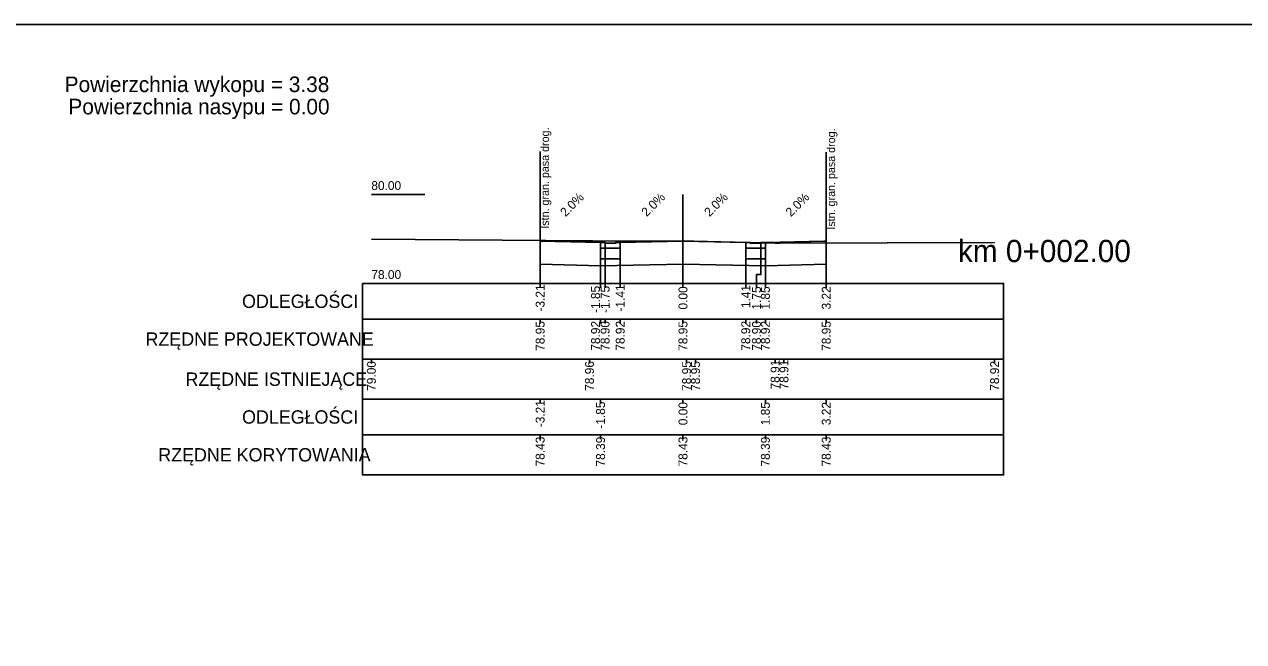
# Model space of a CAD drawing. Extents: x 7492871 to 7493499, y 5802964 to 5802992.
# Drawn here: x 7493302.12 to 7493329.51, y 5802978.41 to 5802992.28 of the extents above; entities that cross this region are included whole.
import ezdxf

# ---------------------------------------------------------------- set-up
doc = ezdxf.new("R2010")
doc.units = 0
for name, color, linetype in [('_wydruk', 7, 'Continuous'), ('d_pop_nasyp_opis', 7, 'Continuous'), ('d_pop_wykop_opis', 7, 'Continuous'), ('opisy_ramki_pop', 7, 'Continuous'), ('pop_comp_kostka', 7, 'Continuous'), ('pop_comp_lawa', 7, 'Continuous'), ('pop_comp_scieralna', 7, 'Continuous'), ('pop_granica_istn', 7, 'Continuous'), ('pop_opis', 7, 'Continuous'), ('pop_os', 7, 'Continuous'), ('pop_pikietaz', 7, 'Continuous'), ('pop_teren', 7, 'Continuous')]:
    doc.layers.add(name, color=color, linetype=linetype)

msp = doc.modelspace()

# ---------------------------------------------------------------- linework, layer by layer
msp.add_lwpolyline([(7493313.708, 5802987.41), (7493315.011, 5802987.384), (7493315.066, 5802987.383), (7493315.162, 5802987.383), (7493315.166, 5802987.383), (7493315.167, 5802987.363), (7493315.396, 5802987.363), (7493315.406, 5802987.363), (7493315.407, 5802987.383), (7493315.503, 5802987.383), (7493315.507, 5802987.383), (7493316.86, 5802987.41), (7493316.917, 5802987.411), (7493316.975, 5802987.41), (7493318.327, 5802987.383), (7493318.423, 5802987.383), (7493318.427, 5802987.383), (7493318.428, 5802987.363), (7493318.438, 5802987.363), (7493318.667, 5802987.363), (7493318.668, 5802987.383), (7493318.672, 5802987.383), (7493318.768, 5802987.383), (7493320.08, 5802987.409), (7493320.135, 5802987.41)])
at = {"layer": '_wydruk'}
msp.add_lwpolyline([(7492871.369, 5802992.281), (7493499.283, 5802992.281), (7493499.283, 5802963.881), (7492871.369, 5802963.881)], close=True, dxfattribs=at)
at = {"layer": 'opisy_ramki_pop'}
for points in [[(7493313.708, 5802986.89), (7493313.708, 5802986.659), (7493313.708, 5802986.659), (7493313.708, 5802986.459)], [(7493315.066, 5802986.854), (7493315.066, 5802986.659), (7493315.066, 5802986.659), (7493315.066, 5802986.459)], [(7493316.917, 5802986.891), (7493316.917, 5802986.659), (7493316.917, 5802986.659), (7493316.917, 5802986.459)], [(7493318.768, 5802986.854), (7493318.768, 5802986.659), (7493318.768, 5802986.659), (7493318.768, 5802986.459)], [(7493320.135, 5802986.89), (7493320.135, 5802986.659), (7493320.135, 5802986.659), (7493320.135, 5802986.459)]]:
    msp.add_lwpolyline(points, dxfattribs=at)
at = {"layer": 'pop_comp_kostka'}
for p, q in [((7493315.166, 5802987.383), (7493315.066, 5802987.383)), ((7493315.066, 5802987.383), (7493315.066, 5802987.253)), ((7493315.167, 5802987.363), (7493315.166, 5802987.383)), ((7493315.407, 5802987.383), (7493315.406, 5802987.363)), ((7493315.507, 5802987.383), (7493315.407, 5802987.383)), ((7493315.507, 5802987.253), (7493315.507, 5802987.383)), ((7493318.427, 5802987.383), (7493318.327, 5802987.383)), ((7493318.327, 5802987.383), (7493318.327, 5802987.253)), ((7493318.428, 5802987.363), (7493318.427, 5802987.383)), ((7493318.668, 5802987.383), (7493318.667, 5802987.363)), ((7493318.768, 5802987.383), (7493318.668, 5802987.383)), ((7493318.768, 5802987.253), (7493318.768, 5802987.383)), ((7493315.066, 5802987.253), (7493315.507, 5802987.253)), ((7493315.406, 5802987.363), (7493315.167, 5802987.363)), ((7493318.327, 5802987.253), (7493318.768, 5802987.253)), ((7493318.667, 5802987.363), (7493318.428, 5802987.363))]:
    msp.add_line(p, q, dxfattribs=at)
at = {"layer": 'pop_comp_lawa'}
for p, q in [((7493315.507, 5802987.253), (7493315.066, 5802987.253)), ((7493315.066, 5802987.253), (7493315.066, 5802987.013)), ((7493315.507, 5802987.013), (7493315.507, 5802987.253)), ((7493318.768, 5802987.253), (7493318.327, 5802987.253)), ((7493318.327, 5802987.253), (7493318.327, 5802987.013)), ((7493318.768, 5802987.013), (7493318.768, 5802987.253)), ((7493315.066, 5802987.013), (7493315.507, 5802987.013)), ((7493318.327, 5802987.013), (7493318.768, 5802987.013))]:
    msp.add_line(p, q, dxfattribs=at)
at = {"layer": 'pop_comp_scieralna'}
for p, q in [((7493315.066, 5802987.383), (7493313.708, 5802987.41)), ((7493313.708, 5802987.41), (7493313.708, 5802986.89)), ((7493315.066, 5802987.013), (7493315.066, 5802987.383)), ((7493316.917, 5802987.411), (7493315.507, 5802987.383)), ((7493315.507, 5802987.383), (7493315.507, 5802987.013)), ((7493316.917, 5802986.891), (7493316.917, 5802987.411)), ((7493318.327, 5802987.383), (7493316.917, 5802987.411)), ((7493316.917, 5802987.411), (7493316.917, 5802986.891)), ((7493318.327, 5802987.013), (7493318.327, 5802987.383)), ((7493320.135, 5802987.41), (7493318.768, 5802987.383)), ((7493318.768, 5802987.383), (7493318.768, 5802987.013)), ((7493320.135, 5802986.89), (7493320.135, 5802987.41)), ((7493313.708, 5802986.89), (7493315.066, 5802986.854)), ((7493315.507, 5802987.013), (7493315.066, 5802987.013)), ((7493315.066, 5802986.854), (7493316.917, 5802986.891)), ((7493316.917, 5802986.891), (7493318.768, 5802986.854)), ((7493318.768, 5802987.013), (7493318.327, 5802987.013)), ((7493318.768, 5802986.854), (7493320.135, 5802986.89))]:
    msp.add_line(p, q, dxfattribs=at)
at = {"layer": 'pop_granica_istn'}
for p, q in [((7493313.708, 5802987.928), (7493313.708, 5802989.428)), ((7493320.135, 5802987.907), (7493320.135, 5802989.407)), ((7493313.708, 5802987.428), (7493313.708, 5802987.928)), ((7493320.135, 5802987.407), (7493320.135, 5802987.907))]:
    msp.add_line(p, q, dxfattribs=at)
at = {"layer": 'pop_opis'}
for p, q in [((7493309.917, 5802988.459), (7493311.117, 5802988.459)), ((7493309.717, 5802986.459), (7493309.717, 5802984.759)), ((7493309.717, 5802986.459), (7493309.717, 5802984.759)), ((7493309.717, 5802986.459), (7493309.717, 5802984.759)), ((7493309.717, 5802986.459), (7493309.717, 5802984.759)), ((7493309.917, 5802986.459), (7493311.117, 5802986.459)), ((7493313.708, 5802986.359), (7493313.708, 5802986.459)), ((7493315.066, 5802986.359), (7493315.066, 5802986.459)), ((7493315.167, 5802986.359), (7493315.167, 5802986.459)), ((7493315.507, 5802986.359), (7493315.507, 5802986.459)), ((7493316.917, 5802986.359), (7493316.917, 5802986.459)), ((7493318.327, 5802986.359), (7493318.327, 5802986.459)), ((7493318.568, 5802986.359), (7493318.568, 5802986.459)), ((7493318.768, 5802986.359), (7493318.768, 5802986.459)), ((7493320.135, 5802986.359), (7493320.135, 5802986.459)), ((7493309.717, 5802985.659), (7493324.117, 5802985.659)), ((7493309.717, 5802985.659), (7493324.117, 5802985.659)), ((7493309.717, 5802985.659), (7493324.117, 5802985.659)), ((7493309.717, 5802985.659), (7493324.117, 5802985.659)), ((7493313.708, 5802985.559), (7493313.708, 5802985.659)), ((7493315.066, 5802985.559), (7493315.066, 5802985.659)), ((7493315.167, 5802985.559), (7493315.167, 5802985.659)), ((7493315.507, 5802985.559), (7493315.507, 5802985.659)), ((7493316.917, 5802985.559), (7493316.917, 5802985.659)), ((7493318.327, 5802985.559), (7493318.327, 5802985.659)), ((7493318.568, 5802985.559), (7493318.568, 5802985.659)), ((7493318.768, 5802985.559), (7493318.768, 5802985.659)), ((7493320.135, 5802985.559), (7493320.135, 5802985.659)), ((7493309.717, 5802984.759), (7493309.717, 5802983.859)), ((7493309.917, 5802984.659), (7493309.917, 5802984.759)), ((7493314.817, 5802984.659), (7493314.817, 5802984.759)), ((7493316.999, 5802984.659), (7493316.999, 5802984.759)), ((7493317.199, 5802984.659), (7493317.199, 5802984.759)), ((7493318.986, 5802984.659), (7493318.986, 5802984.759)), ((7493319.186, 5802984.659), (7493319.186, 5802984.759)), ((7493323.917, 5802984.659), (7493323.917, 5802984.759)), ((7493309.717, 5802983.859), (7493309.717, 5802982.159)), ((7493313.708, 5802983.759), (7493313.708, 5802983.859)), ((7493315.066, 5802983.759), (7493315.066, 5802983.859)), ((7493316.917, 5802983.759), (7493316.917, 5802983.859)), ((7493318.768, 5802983.759), (7493318.768, 5802983.859)), ((7493320.135, 5802983.759), (7493320.135, 5802983.859)), ((7493309.717, 5802983.059), (7493324.117, 5802983.059)), ((7493313.708, 5802982.959), (7493313.708, 5802983.059)), ((7493315.066, 5802982.959), (7493315.066, 5802983.059)), ((7493316.917, 5802982.959), (7493316.917, 5802983.059)), ((7493318.768, 5802982.959), (7493318.768, 5802983.059)), ((7493320.135, 5802982.959), (7493320.135, 5802983.059))]:
    msp.add_line(p, q, dxfattribs=at)
for points in [[(7493313.708, 5802987.41), (7493313.708, 5802986.659), (7493313.708, 5802986.659), (7493313.708, 5802986.459)], [(7493315.066, 5802987.383), (7493315.066, 5802986.659), (7493315.066, 5802986.659), (7493315.066, 5802986.459)], [(7493315.507, 5802987.383), (7493315.507, 5802986.659), (7493315.507, 5802986.659), (7493315.507, 5802986.459)], [(7493316.917, 5802987.411), (7493316.917, 5802986.659), (7493316.917, 5802986.659), (7493316.917, 5802986.459)], [(7493318.327, 5802987.383), (7493318.327, 5802986.659), (7493318.327, 5802986.659), (7493318.327, 5802986.459)], [(7493318.768, 5802987.383), (7493318.768, 5802986.659), (7493318.768, 5802986.659), (7493318.768, 5802986.459)], [(7493320.135, 5802987.41), (7493320.135, 5802986.659), (7493320.135, 5802986.659), (7493320.135, 5802986.459)], [(7493315.167, 5802987.363), (7493315.167, 5802986.659), (7493315.167, 5802986.659), (7493315.167, 5802986.459)], [(7493318.667, 5802987.363), (7493318.667, 5802986.659), (7493318.568, 5802986.659), (7493318.568, 5802986.459)]]:
    msp.add_lwpolyline(points, dxfattribs=at)
for points in [[(7493309.717, 5802986.459), (7493309.717, 5802984.759), (7493324.117, 5802984.759), (7493324.117, 5802986.459)], [(7493309.717, 5802986.459), (7493309.717, 5802984.759), (7493324.117, 5802984.759), (7493324.117, 5802986.459)], [(7493309.717, 5802986.459), (7493309.717, 5802984.759), (7493324.117, 5802984.759), (7493324.117, 5802986.459)], [(7493309.717, 5802986.459), (7493309.717, 5802984.759), (7493324.117, 5802984.759), (7493324.117, 5802986.459)], [(7493309.717, 5802984.759), (7493309.717, 5802983.859), (7493324.117, 5802983.859), (7493324.117, 5802984.759)], [(7493309.717, 5802983.859), (7493309.717, 5802982.159), (7493324.117, 5802982.159), (7493324.117, 5802983.859)]]:
    msp.add_lwpolyline(points, close=True, dxfattribs=at)
at = {"layer": 'pop_os'}
msp.add_line((7493316.917, 5802988.459), (7493316.917, 5802986.459), dxfattribs=at)
at = {"layer": 'pop_teren'}
msp.add_lwpolyline([(7493309.917, 5802987.458), (7493314.817, 5802987.417), (7493314.883, 5802987.414), (7493316.999, 5802987.408), (7493317.161, 5802987.408), (7493318.986, 5802987.365), (7493319.091, 5802987.366), (7493323.917, 5802987.376)], dxfattribs=at)

# ---------------------------------------------------------------- texts
at = {"layer": 'd_pop_nasyp_opis'}
msp.add_text('Powierzchnia nasypu = 0.00', height=0.35, dxfattribs=at).set_placement((7493303.112, 5802990.259))
at = {"layer": 'd_pop_wykop_opis'}
msp.add_text('Powierzchnia wykopu = 3.38', height=0.35, dxfattribs=at).set_placement((7493303.029, 5802990.759))
at = {"layer": 'pop_granica_istn'}
for p in [(7493313.906, 5802987.689), (7493320.334, 5802987.668)]:
    msp.add_text('Istn. gran. pasa drog.', height=0.18, rotation=90, dxfattribs=at).set_placement(p)
at = {"layer": 'pop_opis'}
for s, height, p in [('80.00', 0.2, (7493309.917, 5802988.559)), ('78.00', 0.2, (7493309.917, 5802986.559)), ('ODLEGŁOŚCI', 0.3, (7493307.013, 5802985.909)), ('ODLEGŁOŚCI', 0.3, (7493307.013, 5802985.909)), ('ODLEGŁOŚCI', 0.3, (7493307.013, 5802985.909)), ('ODLEGŁOŚCI', 0.3, (7493307.013, 5802985.909)), ('RZĘDNE PROJEKTOWANE', 0.3, (7493304.845, 5802985.059)), ('RZĘDNE PROJEKTOWANE', 0.3, (7493304.845, 5802985.059)), ('RZĘDNE PROJEKTOWANE', 0.3, (7493304.845, 5802985.059)), ('RZĘDNE PROJEKTOWANE', 0.3, (7493304.845, 5802985.059)), ('RZĘDNE ISTNIEJĄCE', 0.3, (7493305.742, 5802984.159)), ('ODLEGŁOŚCI', 0.3, (7493307.013, 5802983.309)), ('RZĘDNE KORYTOWANIA', 0.3, (7493305.131, 5802982.459))]:
    msp.add_text(s, height=height, dxfattribs=at).set_placement(p)
for s, rotation, p in [('2.0%', 45, (7493314.278, 5802987.946)), ('2.0%', 45, (7493316.103, 5802987.947)), ('2.0%', 45, (7493317.513, 5802987.947)), ('2.0%', 45, (7493319.343, 5802987.946)), ('-3.21', 90, (7493313.808, 5802985.829)), ('-1.85', 90, (7493315.053, 5802985.796)), ('-1.75', 90, (7493315.267, 5802985.796)), ('-1.41', 90, (7493315.607, 5802985.829)), ('0.00', 90, (7493317.017, 5802985.874)), ('1.41', 90, (7493318.427, 5802985.905)), ('1.75', 90, (7493318.668, 5802985.873)), ('1.85', 90, (7493318.868, 5802985.873)), ('3.22', 90, (7493320.235, 5802985.875)), ('78.95', 90, (7493313.808, 5802984.945)), ('78.92', 90, (7493315.053, 5802984.948)), ('78.90', 90, (7493315.267, 5802984.947)), ('78.92', 90, (7493315.607, 5802984.948)), ('78.95', 90, (7493317.017, 5802984.945)), ('78.92', 90, (7493318.427, 5802984.948)), ('78.90', 90, (7493318.668, 5802984.947)), ('78.92', 90, (7493318.868, 5802984.948)), ('78.95', 90, (7493320.235, 5802984.945)), ('79.00', 90, (7493310.017, 5802984.047)), ('78.96', 90, (7493314.917, 5802984.047)), ('78.95', 90, (7493317.099, 5802984.045)), ('78.95', 90, (7493317.299, 5802984.045)), ('78.91', 90, (7493319.086, 5802984.078)), ('78.91', 90, (7493319.286, 5802984.078)), ('78.92', 90, (7493324.017, 5802984.048)), ('-3.21', 90, (7493313.808, 5802983.229)), ('-1.85', 90, (7493315.166, 5802983.196)), ('0.00', 90, (7493317.017, 5802983.274)), ('1.85', 90, (7493318.868, 5802983.273)), ('3.22', 90, (7493320.235, 5802983.275)), ('78.43', 90, (7493313.808, 5802982.347)), ('78.39', 90, (7493315.166, 5802982.346)), ('78.43', 90, (7493317.017, 5802982.347)), ('78.39', 90, (7493318.868, 5802982.346)), ('78.43', 90, (7493320.235, 5802982.347))]:
    msp.add_text(s, height=0.2, rotation=rotation, dxfattribs=at).set_placement(p)
at = {"layer": 'pop_pikietaz'}
msp.add_text('km 0+002.00', height=0.5, dxfattribs=at).set_placement((7493323.093, 5802986.939))

doc.saveas('drawing.dxf')
